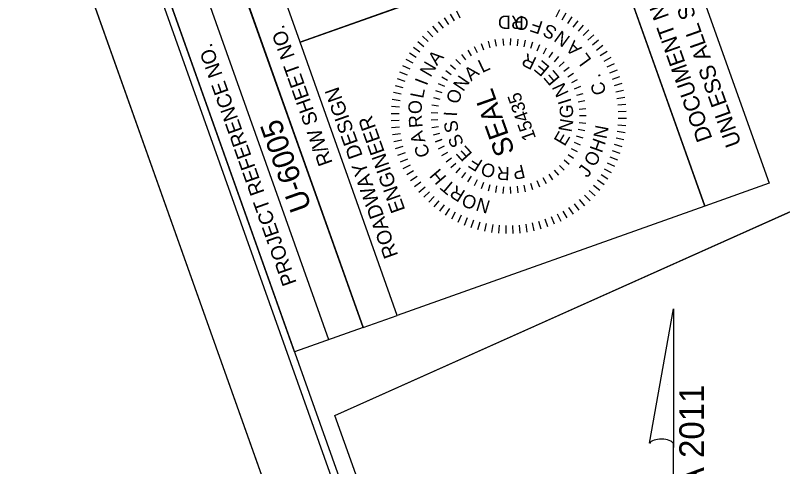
# Model space of a CAD drawing. Extents: x 1615843 to 1617444, y 901957 to 903921.
# Drawn here: x 1615843 to 1616107.5, y 903316.7 to 903472.3 of the extents above; entities that cross this region are included whole.
import ezdxf

# ---------------------------------------------------------------- set-up
doc = ezdxf.new("R2010")
doc.units = 0
for name, color, linetype in [('Exist Plan Preparation Drainage Flow Arrows', 7, 'Continuous'), ('Exist Plan Preparation Drainage Notes Label', 7, 'Continuous'), ('Exist Structure Minor Pipes CMP 15 Inch Text', 7, 'Continuous'), ('Exist Structure Minor Pipes CMP 24 Inch Text', 7, 'Continuous'), ('Exist Structure Minor Pipes RCP 15 Inch', 7, 'Continuous'), ('Exist Structure Minor Pipes RCP 24 Inch Text', 7, 'Continuous'), ('Prop Drainage Structure Catch Basin Grate 840 03E CELL', 7, 'Continuous'), ('Prop Plan Preparation Cover Label', 7, 'Continuous'), ('Prop Plan Preparation Crest Label', 7, 'Continuous'), ('Scratch_Level_7', 7, 'Continuous')]:
    doc.layers.add(name, color=color, linetype=linetype)

msp = doc.modelspace()

# ---------------------------------------------------------------- linework, layer by layer
at = {"layer": 'Exist Plan Preparation Drainage Flow Arrows'}
msp.add_lwpolyline([(1615865.68, 903555.66), (1616423.91, 901985.43), (1617418.05, 902338.86), (1616859.83, 903909.09)], close=True, dxfattribs=at)
at = {"layer": 'Exist Plan Preparation Drainage Notes Label'}
msp.add_lwpolyline([(1615843.02, 903552.38), (1616407.11, 901965.67), (1617443.56, 902334.13), (1616879.47, 903920.85)], close=True, dxfattribs=at)
at = {"layer": 'Exist Structure Minor Pipes CMP 15 Inch Text'}
for p, q in [((1616035.8, 903602.86), (1616102.8, 903414.38)), ((1616080.66, 903406.51), (1616013.66, 903594.99)), ((1616102.8, 903414.38), (1616080.66, 903406.51))]:
    msp.add_line(p, q, dxfattribs=at)
at = {"layer": 'Exist Structure Minor Pipes CMP 24 Inch Text'}
msp.add_line((1615843.02, 903552.38), (1616407.11, 901965.67), dxfattribs=at)
at = {"layer": 'Exist Structure Minor Pipes RCP 15 Inch'}
for p, q in [((1616061.62, 903324.72), (1616069.82, 903371.07)), ((1616069.87, 903371.07), (1616069.87, 903323.27)), ((1616067.94, 903345.06), (1616067.89, 903345.06)), ((1616067.94, 903345.06), (1616067.89, 903345.06)), ((1616069.87, 903298.47), (1616069.87, 903324.67)), ((1616069.87, 903323.27), (1616069.87, 903324.62))]:
    msp.add_line(p, q, dxfattribs=at)
msp.add_ellipse((1616065.76, 903324.22), major_axis=(4.23, -0.03), ratio=0.461098, start_param=0.216388, end_param=2.908219, dxfattribs=at)
at = {"layer": 'Exist Structure Minor Pipes RCP 24 Inch Text'}
msp.add_line((1615953.12, 903334.31), (1616903.33, 903759.78), dxfattribs=at)
at = {"layer": 'Prop Drainage Structure Catch Basin Grate 840 03E CELL'}
for p, q in [((1615995.03, 903473.89), (1615996.26, 903471.42)), ((1616030.54, 903474.17), (1616029.35, 903471.68)), ((1615990.79, 903471.46), (1615992.3, 903469.15)), ((1615992.87, 903472.74), (1615994.25, 903470.34)), ((1616032.71, 903473.05), (1616031.38, 903470.63)), ((1616034.82, 903471.8), (1616033.34, 903469.47)), ((1615986.86, 903468.52), (1615988.65, 903466.41)), ((1615988.78, 903470.05), (1615990.43, 903467.83)), ((1616036.85, 903470.43), (1616035.23, 903468.19)), ((1616038.79, 903468.93), (1616037.04, 903466.79)), ((1615985.05, 903466.88), (1615986.95, 903464.88)), ((1616040.64, 903467.32), (1616038.76, 903465.29)), ((1615981.71, 903463.29), (1615983.85, 903461.54)), ((1615983.32, 903465.14), (1615985.35, 903463.26)), ((1616006, 903463.35), (1616006.61, 903461.13)), ((1616008.84, 903461.63), (1616008.44, 903463.9)), ((1616011.09, 903464.23), (1616011.26, 903461.93)), ((1616013.67, 903464.3), (1616013.62, 903461.99)), ((1616016.25, 903464.11), (1616015.97, 903461.83)), ((1616018.79, 903463.68), (1616018.3, 903461.43)), ((1616042.38, 903465.6), (1616040.38, 903463.69)), ((1616044.02, 903463.78), (1616041.91, 903461.99)), ((1615980.22, 903461.35), (1615982.46, 903459.73)), ((1616001.18, 903461.51), (1616002.2, 903459.45)), ((1616003.55, 903462.55), (1616004.37, 903460.4)), ((1616021.29, 903463.01), (1616020.58, 903460.82)), ((1616023.7, 903462.1), (1616022.79, 903459.99)), ((1616026.02, 903460.96), (1616024.9, 903458.94)), ((1616045.55, 903461.87), (1616043.33, 903460.21)), ((1615978.84, 903459.32), (1615981.18, 903457.84)), ((1615996.81, 903458.78), (1615998.21, 903456.95)), ((1615998.93, 903460.25), (1616000.15, 903458.3)), ((1616028.21, 903459.6), (1616026.91, 903457.7)), ((1616030.27, 903458.04), (1616028.79, 903456.27)), ((1616046.96, 903459.86), (1616044.65, 903458.34)), ((1615977.59, 903457.21), (1615980.01, 903455.88)), ((1615993.03, 903455.26), (1615994.76, 903453.74)), ((1615994.83, 903457.11), (1615996.41, 903455.43)), ((1616032.16, 903456.28), (1616030.52, 903454.66)), ((1616048.24, 903457.77), (1616045.84, 903456.4)), ((1616049.39, 903455.61), (1616046.92, 903454.39)), ((1615975.48, 903452.8), (1615978.05, 903451.76)), ((1615976.47, 903455.04), (1615978.97, 903453.85)), ((1615991.42, 903453.24), (1615993.29, 903451.9)), ((1616033.88, 903454.35), (1616032.09, 903452.9)), ((1616050.42, 903453.39), (1616047.87, 903452.31)), ((1615974.63, 903450.5), (1615977.25, 903449.62)), ((1615990.01, 903451.08), (1615991.99, 903449.92)), ((1616035.4, 903452.26), (1616033.48, 903450.99)), ((1616036.72, 903450.04), (1616034.68, 903448.96)), ((1616051.3, 903451.1), (1616048.7, 903450.18)), ((1615973.92, 903448.15), (1615976.59, 903447.43)), ((1615988.81, 903448.79), (1615990.91, 903447.82)), ((1616037.81, 903447.7), (1616035.68, 903446.83)), ((1616052.05, 903448.77), (1616049.4, 903448.01)), ((1615973.35, 903445.77), (1615976.06, 903445.21)), ((1615987.84, 903446.4), (1615990.02, 903445.64)), ((1616038.67, 903445.26), (1616036.47, 903444.6)), ((1616052.65, 903446.4), (1616049.96, 903445.79)), ((1615972.93, 903443.36), (1615975.67, 903442.96)), ((1615987.11, 903443.92), (1615989.35, 903443.38)), ((1616039.29, 903442.76), (1616037.03, 903442.31)), ((1616053.12, 903443.99), (1616050.39, 903443.55)), ((1615972.66, 903440.92), (1615975.41, 903440.7)), ((1615986.62, 903441.39), (1615988.9, 903441.06)), ((1616037.38, 903439.96), (1616039.68, 903440.19)), ((1616053.43, 903441.56), (1616050.68, 903441.29)), ((1615972.53, 903438.48), (1615975.29, 903438.41)), ((1615986.37, 903438.81), (1615988.67, 903438.71)), ((1616039.8, 903437.62), (1616037.5, 903437.62)), ((1616053.6, 903439.12), (1616050.83, 903439.01)), ((1616053.62, 903436.67), (1616050.85, 903436.73)), ((1615972.54, 903436.03), (1615975.31, 903436.14)), ((1615986.38, 903436.23), (1615988.68, 903436.35)), ((1616039.68, 903435.04), (1616037.39, 903435.26)), ((1616053.49, 903434.22), (1616050.73, 903434.45)), ((1615972.71, 903433.58), (1615975.46, 903433.86)), ((1615973.03, 903431.15), (1615975.76, 903431.59)), ((1615986.63, 903433.66), (1615988.91, 903434)), ((1615987.13, 903431.13), (1615989.37, 903431.68)), ((1616039.31, 903432.48), (1616037.05, 903432.92)), ((1616053.21, 903431.79), (1616050.48, 903432.18)), ((1615973.49, 903428.75), (1615976.19, 903429.35)), ((1615987.88, 903428.65), (1615990.05, 903429.42)), ((1615990.05, 903429.42), (1615987.88, 903428.65)), ((1616038.7, 903429.98), (1616036.49, 903430.63)), ((1616052.79, 903429.37), (1616050.08, 903429.93)), ((1615974.09, 903426.38), (1615976.75, 903427.14)), ((1615988.86, 903426.26), (1615990.94, 903427.24)), ((1616036.76, 903425.2), (1616034.72, 903426.26)), ((1616037.85, 903427.54), (1616035.71, 903428.4)), ((1616052.22, 903426.99), (1616049.56, 903427.71)), ((1615974.84, 903424.04), (1615977.45, 903424.96)), ((1615990.06, 903423.98), (1615992.04, 903425.15)), ((1616035.46, 903422.97), (1616033.53, 903424.23)), ((1616051.51, 903424.65), (1616048.89, 903425.53)), ((1615975.73, 903421.76), (1615978.28, 903422.83)), ((1615991.48, 903421.82), (1615993.34, 903423.18)), ((1615993.1, 903419.81), (1615994.82, 903421.34)), ((1616033.94, 903420.87), (1616032.15, 903422.31)), ((1616049.67, 903420.11), (1616047.18, 903421.3)), ((1616050.66, 903422.35), (1616048.1, 903423.39)), ((1615976.75, 903419.53), (1615979.23, 903420.76)), ((1615977.91, 903417.37), (1615980.3, 903418.75)), ((1615994.91, 903417.97), (1615996.47, 903419.65)), ((1616030.35, 903417.18), (1616028.86, 903418.93)), ((1616032.23, 903418.94), (1616030.58, 903420.54)), ((1616048.55, 903417.93), (1616046.14, 903419.27)), ((1615979.19, 903415.29), (1615981.5, 903416.8)), ((1615996.88, 903416.3), (1615998.28, 903418.14)), ((1615999.01, 903414.84), (1616000.23, 903416.8)), ((1616001.27, 903413.59), (1616002.29, 903415.66)), ((1616026.11, 903414.24), (1616024.98, 903416.25)), ((1616028.3, 903415.6), (1616026.99, 903417.5)), ((1616047.3, 903415.82), (1616044.97, 903417.3)), ((1615980.6, 903413.28), (1615982.82, 903414.93)), ((1615982.12, 903411.36), (1615984.23, 903413.15)), ((1616003.64, 903412.56), (1616004.45, 903414.72)), ((1616006.1, 903411.77), (1616006.7, 903413.99)), ((1616008.62, 903411.22), (1616009.01, 903413.49)), ((1616011.19, 903410.91), (1616011.35, 903413.21)), ((1616013.77, 903410.85), (1616013.71, 903413.16)), ((1616016.34, 903411.04), (1616016.06, 903413.33)), ((1616018.89, 903411.48), (1616018.39, 903413.73)), ((1616021.38, 903412.17), (1616020.67, 903414.36)), ((1616023.79, 903413.09), (1616022.87, 903415.2)), ((1616044.43, 903411.86), (1616042.29, 903413.61)), ((1616045.93, 903413.8), (1616043.69, 903415.42)), ((1615983.77, 903409.55), (1615985.76, 903411.45)), ((1616041.1, 903408.27), (1616039.19, 903410.26)), ((1616042.82, 903410.01), (1616040.79, 903411.89)), ((1615985.51, 903407.82), (1615987.39, 903409.85)), ((1615987.36, 903406.21), (1615989.11, 903408.35)), ((1616039.28, 903406.62), (1616037.49, 903408.73)), ((1615989.3, 903404.72), (1615990.92, 903406.96)), ((1615991.32, 903403.34), (1615992.8, 903405.68)), ((1616035.36, 903403.69), (1616033.84, 903406)), ((1616037.37, 903405.1), (1616035.71, 903407.31)), ((1615993.43, 903402.09), (1615994.77, 903404.51)), ((1615995.61, 903400.97), (1615996.8, 903403.47)), ((1615997.85, 903399.98), (1615998.89, 903402.54)), ((1616028.89, 903400.23), (1616027.81, 903402.77)), ((1616031.11, 903401.25), (1616029.89, 903403.73)), ((1616033.27, 903402.41), (1616031.9, 903404.8)), ((1616000.15, 903399.13), (1616001.03, 903401.75)), ((1616002.49, 903398.42), (1616003.21, 903401.09)), ((1616004.87, 903397.85), (1616005.44, 903400.56)), ((1616007.29, 903397.43), (1616007.68, 903400.17)), ((1616009.72, 903397.16), (1616009.95, 903399.91)), ((1616012.17, 903397.03), (1616012.23, 903399.79)), ((1616014.62, 903397.04), (1616014.51, 903399.81)), ((1616017.06, 903397.21), (1616016.79, 903399.96)), ((1616019.49, 903397.53), (1616019.05, 903400.26)), ((1616021.9, 903397.99), (1616021.29, 903400.69)), ((1616024.27, 903398.59), (1616023.51, 903401.25)), ((1616026.6, 903399.34), (1616025.68, 903401.95))]:
    msp.add_line(p, q, dxfattribs=at)
at = {"layer": 'Prop Plan Preparation Cover Label'}
for p, q in [((1615962.88, 903364.63), (1615895.87, 903553.13)), ((1615962.88, 903364.63), (1615895.87, 903553.13)), ((1615951.11, 903360.45), (1615884.09, 903548.94)), ((1615941.15, 903463.09), (1616047.1, 903500.76)), ((1615962.88, 903364.63), (1615974.66, 903368.82))]:
    msp.add_line(p, q, dxfattribs=at)
for points in [[(1615872.27, 903544.74), (1616374.72, 902131.39), (1617364.06, 902483.11), (1616861.61, 903896.45)], [(1615941.15, 903463.09), (1615907.65, 903557.31), (1616013.65, 903595), (1616047.15, 903500.78)], [(1615939.28, 903356.24), (1615872.27, 903544.74), (1615895.87, 903553.13), (1615962.88, 903364.63)], [(1615974.66, 903368.82), (1615941.15, 903463.09), (1616047.15, 903500.78), (1616080.66, 903406.51)]]:
    msp.add_lwpolyline(points, close=True, dxfattribs=at)
at = {"layer": 'Prop Plan Preparation Crest Label'}
msp.add_lwpolyline([(1616920.55, 902382.99), (1616299.46, 902356.07), (1616191.22, 902669.1), (1615953.12, 903334.31), (1616369.18, 903520.6), (1616903.33, 903759.78), (1617120.19, 903154.34), (1617263.37, 902747.79), (1617083.45, 902390.05)], close=True, dxfattribs=at)

# ---------------------------------------------------------------- texts
at = {"layer": 'Exist Structure Minor Pipes CMP 15 Inch Text'}
for s, p in [('UNLESS ALL SIGNATURES COMPLETED', (1616093.34, 903427.99)), ('DOCUMENT NOT CONSIDERED FINAL', (1616083.35, 903429.82))]:
    msp.add_text(s, height=5.5, rotation=109.5707, dxfattribs=at).set_placement(p)
at = {"layer": 'Exist Structure Minor Pipes RCP 15 Inch'}
msp.add_text('NAD 83/NA 2011', height=8.5, rotation=90, dxfattribs=at).set_placement((1616080.39, 903257.76))
at = {"layer": 'Prop Drainage Structure Catch Basin Grate 840 03E CELL'}
for s, height, rotation, p in [(' RD', 4.603, 179.1633, (1616020.01, 903472.08)), ('O ', 4.603, 170.4905, (1616020.25, 903471.45)), ('F', 4.6, 161.6979, (1616025.18, 903470.01)), ('S', 4.6, 152.8153, (1616030.14, 903467.7)), ('N', 4.6, 143.9326, (1616034.59, 903464.71)), ('A', 4.6, 135.11, (1616038.55, 903461.04)), ('A', 4.6, 50.0079, (1615988.32, 903454.72)), ('R', 4.6, 154.0557, (1616023.05, 903457.46)), ('L', 4.6, 126.1075, (1616041.8, 903456.91)), ('N', 4.6, 59.7755, (1615986.13, 903450.72)), ('L', 4.6, 25.3615, (1616003.93, 903452.34)), ('E', 4.6, 140.2847, (1616027.54, 903454.4)), ('A', 4.6, 40.6577, (1616000.13, 903449.41)), ('E', 4.6, 130.2988, (1616030.97, 903450.6)), ('I', 4.6, 69.0699, (1615984.85, 903447.83)), ('N', 4.6, 55.954, (1615997.42, 903445.77)), ('.', 4.6, 113.3231, (1616044.99, 903450.94)), ('N', 4.6, 114.9067, (1616033.88, 903445.45)), ('C', 4.6, 105.5808, (1616046.78, 903445.5)), ('L', 4.6, 78.6454, (1615983.57, 903443.43)), ('O', 4.6, 71.2502, (1615995.7, 903441.4)), ('SEAL', 6.91, 109.4908, (1616015.25, 903425.21)), ('15435', 4.603, 109.4908, (1616022.54, 903429.98)), ('O', 4.6, 91.7817, (1615983.2, 903438.33)), ('I', 4.6, 107.277, (1616034.78, 903442.45)), ('G', 4.6, 89.1822, (1616035.22, 903436.79)), ('R', 4.6, 94.8385, (1615983.44, 903433.69)), ('I', 4.6, 86.5465, (1615995.25, 903437.3)), ('S', 4.6, 101.8427, (1615995.94, 903432.36)), ('N', 4.6, 80.416, (1616034.69, 903431.82)), ('N', 4.6, 78.813, (1616046.74, 903429.47)), ('A', 4.6, 106.8478, (1615984.43, 903428.86)), ('E', 4.6, 59.5609, (1616032.36, 903426.9)), ('S', 4.6, 117.139, (1615997.84, 903428.15)), ('H', 4.6, 70.1404, (1616045.17, 903424.59)), ('C', 4.6, 106.8478, (1615986.02, 903424.09)), ('E', 4.6, 132.4352, (1616000.77, 903424.6)), ('O', 4.6, 61.4977, (1616042.77, 903419.75)), ('F', 4.6, 147.7315, (1616004.46, 903422)), ('O', 4.6, 163.0277, (1616008.98, 903420.35)), ('J', 4.6, 53.4259, (1616040.19, 903416.05)), ('H', 4.6, 130.5585, (1615991.87, 903416.44)), ('R', 4.6, 178.324, (1616013.48, 903420.02)), ('P', 4.6, 193.6202, (1616018.02, 903420.88)), ('T', 4.6, 139.9904, (1615994.99, 903413.62)), ('R', 4.6, 148.1514, (1615998.45, 903411.56)), ('O', 4.6, 161.2081, (1616002.49, 903409.45)), ('N', 4.6, 163.1676, (1616007.04, 903408.25))]:
    msp.add_text(s, height=height, rotation=rotation, dxfattribs=at).set_placement(p)
at = {"layer": 'Prop Plan Preparation Cover Label'}
for s, height, p in [('R/W SHEET NO.', 5.0001, (1615952.46, 903421.42)), ('PROJECT REFERENCE NO.', 5.0001, (1615940.04, 903380.07)), ('ROADWAY DESIGN', 5.0001, (1615975.04, 903389.55)), ('ENGINEER', 5, (1615977.48, 903405.22))]:
    msp.add_text(s, height=height, rotation=109.5707, dxfattribs=at).set_placement(p)
at = {"layer": 'Scratch_Level_7'}
msp.add_text('U-6005', height=7.5, rotation=109.5707, dxfattribs=at).set_placement((1615945.24, 903406.05))

doc.saveas('drawing.dxf')
